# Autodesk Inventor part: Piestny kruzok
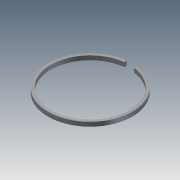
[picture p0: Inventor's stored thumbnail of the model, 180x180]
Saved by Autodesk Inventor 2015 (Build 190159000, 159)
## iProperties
Created: 2012-10
Part Number: Piestny kruzok
Material: Všeobecné
Document SubType Name: Modeling
Designer: Marián Mičúch
Density: 1 g/cm^3
Appearance: Výchozí
Author: Marián Mičúch
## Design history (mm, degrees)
sketch "Náčrt1"
  geometry: C1 r 15 at (0, 14.5) reference; C2 r 14 at (0, 14.5) reference; 1 further point
  dimensions: "d0" = 30 diameter of C1 (derived); "d1" = 28 diameter of C2 (derived)
  node "Referenční1"
  node "Referenční2"
node "Pracovní rovina1"
extrude "Vysunutí1" new body sketch "Náčrt1" stored distance "d2" = 10; taper "d3" = 0 deg
sketch "Náčrt2"
  geometry: L1 (0, 0)-(2.503, 20.388); L2 (0, 0)-(0, 20.8); L3 (0, 0)-(-2.503, 20.388); L4 (-2.503, 20.388)-(2.503, 20.388); C1 r 15 at (0, 0) reference; 1 further point
  constraints: 8 end point, 1 perpendicular, 1 symmetric about line, 1 vertical
  dimensions: "d4" = 7 deg angle of L1 L2
extrude "Vysunutí2" cut sketch "Náčrt2" stored distance "d5" = 10; taper "d6" = 0 deg
node "Těleso1"
